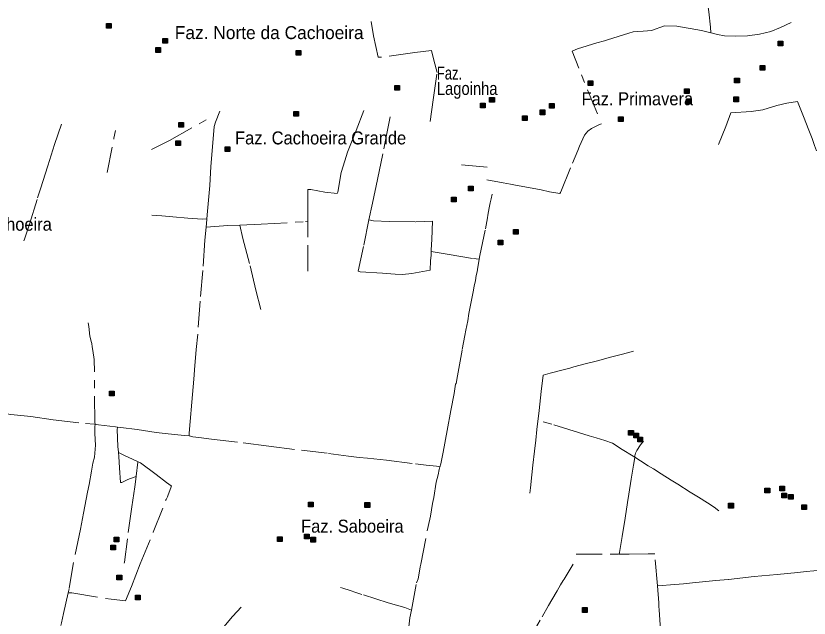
# Model space of a CAD drawing. Extents: x 393.5 to 446.9, y 8064.8 to 8120.4.
# Drawn here: x 415.2 to 425, y 8086.21 to 8093.64 of the extents above; entities that cross this region are included whole.
import ezdxf

# ---------------------------------------------------------------- set-up
doc = ezdxf.new("R2010")
doc.units = 0
doc.header["$LTSCALE"] = 0.064
doc.linetypes.add('DOT_DASHED', pattern=[7.7, 5, -1.2, 0.3, -1.2])
doc.layers.add('2', color=7, linetype='Continuous', lineweight=25)
doc.layers.add('22', color=7, linetype='DOT_DASHED', lineweight=13)
doc.layers.add('61', color=7, linetype='Continuous')

msp = doc.modelspace()

# ---------------------------------------------------------------- hatches: boundary and pattern name
at = {"layer": '2'}
for points in [[(416.3204, 8093.5485), (416.3784, 8093.5485), (416.3784, 8093.4905), (416.3204, 8093.4905)], [(417.0173, 8093.3619), (417.0753, 8093.3619), (417.0753, 8093.3039), (417.0173, 8093.3039)], [(424.6135, 8093.3276), (424.6715, 8093.3276), (424.6715, 8093.2696), (424.6135, 8093.2696)], [(416.9306, 8093.2488), (416.9886, 8093.2488), (416.9886, 8093.1908), (416.9306, 8093.1908)], [(418.6616, 8093.2136), (418.7196, 8093.2136), (418.7196, 8093.1556), (418.6616, 8093.1556)], [(424.3893, 8093.027), (424.4473, 8093.027), (424.4473, 8092.969), (424.3893, 8092.969)], [(422.2669, 8092.8375), (422.3249, 8092.8375), (422.3249, 8092.7795), (422.2669, 8092.7795)], [(424.0763, 8092.8721), (424.1343, 8092.8721), (424.1343, 8092.8141), (424.0763, 8092.8141)], [(419.8802, 8092.7813), (419.9382, 8092.7813), (419.9382, 8092.7233), (419.8802, 8092.7233)], [(423.4581, 8092.7423), (423.5161, 8092.7423), (423.5161, 8092.6843), (423.4581, 8092.6843)], [(421.0516, 8092.6337), (421.1096, 8092.6337), (421.1096, 8092.5757), (421.0516, 8092.5757)], [(424.0649, 8092.6396), (424.1229, 8092.6396), (424.1229, 8092.5816), (424.0649, 8092.5816)], [(420.9393, 8092.5634), (420.9973, 8092.5634), (420.9973, 8092.5054), (420.9393, 8092.5054)], [(421.792, 8092.5595), (421.85, 8092.5595), (421.85, 8092.5015), (421.792, 8092.5015)], [(423.4825, 8092.6149), (423.5405, 8092.6149), (423.5405, 8092.5569), (423.4825, 8092.5569)], [(418.6337, 8092.4601), (418.6917, 8092.4601), (418.6917, 8092.4021), (418.6337, 8092.4021)], [(421.6764, 8092.4793), (421.7344, 8092.4793), (421.7344, 8092.4213), (421.6764, 8092.4213)], [(421.4586, 8092.4089), (421.5166, 8092.4089), (421.5166, 8092.3509), (421.4586, 8092.3509)], [(422.6422, 8092.3944), (422.7002, 8092.3944), (422.7002, 8092.3364), (422.6422, 8092.3364)], [(417.2164, 8092.3236), (417.2744, 8092.3236), (417.2744, 8092.2656), (417.2164, 8092.2656)], [(417.1778, 8092.0993), (417.2358, 8092.0993), (417.2358, 8092.0413), (417.1778, 8092.0413)], [(417.7874, 8092.0233), (417.8454, 8092.0233), (417.8454, 8091.9653), (417.7874, 8091.9653)], [(420.7916, 8091.5372), (420.8496, 8091.5372), (420.8496, 8091.4792), (420.7916, 8091.4792)], [(420.5814, 8091.4037), (420.6394, 8091.4037), (420.6394, 8091.3457), (420.5814, 8091.3457)], [(421.3466, 8091.0041), (421.4046, 8091.0041), (421.4046, 8090.9461), (421.3466, 8090.9461)], [(421.1572, 8090.8707), (421.2152, 8090.8707), (421.2152, 8090.8127), (421.1572, 8090.8127)], [(416.3583, 8089.0062), (416.4163, 8089.0062), (416.4163, 8088.9482), (416.3583, 8088.9482)], [(422.7676, 8088.5222), (422.8256, 8088.5222), (422.8256, 8088.4642), (422.7676, 8088.4642)], [(422.83, 8088.4886), (422.888, 8088.4886), (422.888, 8088.4306), (422.83, 8088.4306)], [(422.8792, 8088.4417), (422.9372, 8088.4417), (422.9372, 8088.3837), (422.8792, 8088.3837)], [(424.6356, 8087.8336), (424.6936, 8087.8336), (424.6936, 8087.7756), (424.6356, 8087.7756)], [(424.4508, 8087.8113), (424.5088, 8087.8113), (424.5088, 8087.7533), (424.4508, 8087.7533)], [(424.6567, 8087.7493), (424.7147, 8087.7493), (424.7147, 8087.6913), (424.6567, 8087.6913)], [(424.7416, 8087.7304), (424.7996, 8087.7304), (424.7996, 8087.6724), (424.7416, 8087.6724)], [(418.8136, 8087.6368), (418.8716, 8087.6368), (418.8716, 8087.5788), (418.8136, 8087.5788)], [(419.5128, 8087.6311), (419.5708, 8087.6311), (419.5708, 8087.5731), (419.5128, 8087.5731)], [(424.0022, 8087.6228), (424.0602, 8087.6228), (424.0602, 8087.5648), (424.0022, 8087.5648)], [(424.9044, 8087.603), (424.9624, 8087.603), (424.9624, 8087.545), (424.9044, 8087.545)], [(418.7651, 8087.244), (418.8231, 8087.244), (418.8231, 8087.186), (418.7651, 8087.186)], [(416.4172, 8087.2035), (416.4752, 8087.2035), (416.4752, 8087.1455), (416.4172, 8087.1455)], [(418.434, 8087.2093), (418.492, 8087.2093), (418.492, 8087.1513), (418.434, 8087.1513)], [(418.8452, 8087.203), (418.9032, 8087.203), (418.9032, 8087.145), (418.8452, 8087.145)], [(416.3753, 8087.1052), (416.4333, 8087.1052), (416.4333, 8087.0472), (416.3753, 8087.0472)], [(416.4513, 8086.7357), (416.5093, 8086.7357), (416.5093, 8086.6777), (416.4513, 8086.6777)], [(416.6809, 8086.4891), (416.7389, 8086.4891), (416.7389, 8086.4311), (416.6809, 8086.4311)], [(422.1961, 8086.335), (422.2541, 8086.335), (422.2541, 8086.277), (422.1961, 8086.277)]]:
    msp.add_hatch(color=256, dxfattribs=at).paths.add_polyline_path(points)

# ---------------------------------------------------------------- linework, layer by layer
for points in [[(416.3204, 8093.5485), (416.3784, 8093.5485), (416.3784, 8093.4905), (416.3204, 8093.4905)], [(417.0173, 8093.3619), (417.0753, 8093.3619), (417.0753, 8093.3039), (417.0173, 8093.3039)], [(424.6135, 8093.3276), (424.6715, 8093.3276), (424.6715, 8093.2696), (424.6135, 8093.2696)], [(416.9306, 8093.2488), (416.9886, 8093.2488), (416.9886, 8093.1908), (416.9306, 8093.1908)], [(418.6616, 8093.2136), (418.7196, 8093.2136), (418.7196, 8093.1556), (418.6616, 8093.1556)], [(424.3893, 8093.027), (424.4473, 8093.027), (424.4473, 8092.969), (424.3893, 8092.969)], [(422.2669, 8092.8375), (422.3249, 8092.8375), (422.3249, 8092.7795), (422.2669, 8092.7795)], [(424.0763, 8092.8721), (424.1343, 8092.8721), (424.1343, 8092.8141), (424.0763, 8092.8141)], [(419.8802, 8092.7813), (419.9382, 8092.7813), (419.9382, 8092.7233), (419.8802, 8092.7233)], [(423.4581, 8092.7423), (423.5161, 8092.7423), (423.5161, 8092.6843), (423.4581, 8092.6843)], [(421.0516, 8092.6337), (421.1096, 8092.6337), (421.1096, 8092.5757), (421.0516, 8092.5757)], [(424.0649, 8092.6396), (424.1229, 8092.6396), (424.1229, 8092.5816), (424.0649, 8092.5816)], [(420.9393, 8092.5634), (420.9973, 8092.5634), (420.9973, 8092.5054), (420.9393, 8092.5054)], [(421.792, 8092.5595), (421.85, 8092.5595), (421.85, 8092.5015), (421.792, 8092.5015)], [(423.4825, 8092.6149), (423.5405, 8092.6149), (423.5405, 8092.5569), (423.4825, 8092.5569)], [(418.6337, 8092.4601), (418.6917, 8092.4601), (418.6917, 8092.4021), (418.6337, 8092.4021)], [(421.6764, 8092.4793), (421.7344, 8092.4793), (421.7344, 8092.4213), (421.6764, 8092.4213)], [(421.4586, 8092.4089), (421.5166, 8092.4089), (421.5166, 8092.3509), (421.4586, 8092.3509)], [(422.6422, 8092.3944), (422.7002, 8092.3944), (422.7002, 8092.3364), (422.6422, 8092.3364)], [(417.2164, 8092.3236), (417.2744, 8092.3236), (417.2744, 8092.2656), (417.2164, 8092.2656)], [(417.1778, 8092.0993), (417.2358, 8092.0993), (417.2358, 8092.0413), (417.1778, 8092.0413)], [(417.7874, 8092.0233), (417.8454, 8092.0233), (417.8454, 8091.9653), (417.7874, 8091.9653)], [(420.7916, 8091.5372), (420.8496, 8091.5372), (420.8496, 8091.4792), (420.7916, 8091.4792)], [(420.5814, 8091.4037), (420.6394, 8091.4037), (420.6394, 8091.3457), (420.5814, 8091.3457)], [(421.3466, 8091.0041), (421.4046, 8091.0041), (421.4046, 8090.9461), (421.3466, 8090.9461)], [(421.1572, 8090.8707), (421.2152, 8090.8707), (421.2152, 8090.8127), (421.1572, 8090.8127)], [(416.3583, 8089.0062), (416.4163, 8089.0062), (416.4163, 8088.9482), (416.3583, 8088.9482)], [(422.7676, 8088.5222), (422.8256, 8088.5222), (422.8256, 8088.4642), (422.7676, 8088.4642)], [(422.83, 8088.4886), (422.888, 8088.4886), (422.888, 8088.4306), (422.83, 8088.4306)], [(422.8792, 8088.4417), (422.9372, 8088.4417), (422.9372, 8088.3837), (422.8792, 8088.3837)], [(424.6356, 8087.8336), (424.6936, 8087.8336), (424.6936, 8087.7756), (424.6356, 8087.7756)], [(424.4508, 8087.8113), (424.5088, 8087.8113), (424.5088, 8087.7533), (424.4508, 8087.7533)], [(424.6567, 8087.7493), (424.7147, 8087.7493), (424.7147, 8087.6913), (424.6567, 8087.6913)], [(424.7416, 8087.7304), (424.7996, 8087.7304), (424.7996, 8087.6724), (424.7416, 8087.6724)], [(418.8136, 8087.6368), (418.8716, 8087.6368), (418.8716, 8087.5788), (418.8136, 8087.5788)], [(419.5128, 8087.6311), (419.5708, 8087.6311), (419.5708, 8087.5731), (419.5128, 8087.5731)], [(424.0022, 8087.6228), (424.0602, 8087.6228), (424.0602, 8087.5648), (424.0022, 8087.5648)], [(424.9044, 8087.603), (424.9624, 8087.603), (424.9624, 8087.545), (424.9044, 8087.545)], [(418.7651, 8087.244), (418.8231, 8087.244), (418.8231, 8087.186), (418.7651, 8087.186)], [(416.4172, 8087.2035), (416.4752, 8087.2035), (416.4752, 8087.1455), (416.4172, 8087.1455)], [(418.434, 8087.2093), (418.492, 8087.2093), (418.492, 8087.1513), (418.434, 8087.1513)], [(418.8452, 8087.203), (418.9032, 8087.203), (418.9032, 8087.145), (418.8452, 8087.145)], [(416.3753, 8087.1052), (416.4333, 8087.1052), (416.4333, 8087.0472), (416.3753, 8087.0472)], [(416.4513, 8086.7357), (416.5093, 8086.7357), (416.5093, 8086.6777), (416.4513, 8086.6777)], [(416.6809, 8086.4891), (416.7389, 8086.4891), (416.7389, 8086.4311), (416.6809, 8086.4311)], [(422.1961, 8086.335), (422.2541, 8086.335), (422.2541, 8086.277), (422.1961, 8086.277)]]:
    msp.add_lwpolyline(points, close=True, dxfattribs=at)
at = {"layer": '22'}
for p, q in [((421.021, 8091.7734), (420.6902, 8091.805)), ((416.8813, 8091.1815), (417.0055, 8091.1705)), ((415.3021, 8090.8647), (415.3099, 8090.8841)), ((416.4682, 8088.2515), (416.4737, 8088.2026)), ((422.8443, 8088.1933), (422.8437, 8088.19)), ((423.1221, 8086.6048), (423.1389, 8086.3932))]:
    msp.add_line(p, q, dxfattribs=at)
for points in [[(423.7013, 8094.0907), (423.7164, 8093.9903), (423.7568, 8093.693), (423.7769, 8093.5017), (423.7823, 8093.4313)], [(420.3187, 8092.3382), (420.356, 8092.603), (420.4032, 8092.9402), (420.3612, 8093.0933), (420.3348, 8093.2117), (420.1269, 8093.1899), (419.7158, 8093.1315), (419.6739, 8093.1297), (419.62, 8093.3957), (419.5872, 8093.5724)], [(423.0006, 8093.4562), (423.0516, 8093.459), (423.2091, 8093.519), (423.3643, 8093.5125), (423.6681, 8093.4607), (423.7823, 8093.4313), (423.787, 8093.4301)], [(423.787, 8093.4301), (423.8658, 8093.412), (423.9496, 8093.3937), (424.0899, 8093.3896), (424.2366, 8093.3957), (424.3811, 8093.414), (424.5236, 8093.4465), (424.6409, 8093.4974), (424.7749, 8093.5604)], [(422.3832, 8092.4302), (422.1509, 8092.9958), (422.0713, 8093.2072), (422.1362, 8093.2336), (422.3761, 8093.3098), (422.4714, 8093.3332), (422.5046, 8093.3455), (422.7704, 8093.4264), (422.8228, 8093.4427), (422.873, 8093.4468), (422.9463, 8093.4508), (423.0006, 8093.4562)], [(423.878, 8092.0514), (423.966, 8092.2735), (424.0289, 8092.4449), (424.2789, 8092.4591), (424.3646, 8092.4716), (424.4225, 8092.4799), (424.5962, 8092.5361), (424.7205, 8092.5652), (424.8513, 8092.586), (424.8749, 8092.5215), (424.9242, 8092.3988), (424.9905, 8092.2306), (425.0312, 8092.1266), (425.0633, 8092.0413), (425.0879, 8091.9742)], [(417.5608, 8091.135), (417.567, 8091.2317), (417.596, 8091.5481), (417.6115, 8091.7829), (417.6324, 8092.0226), (417.6517, 8092.2757), (417.6681, 8092.3286), (417.7229, 8092.4655)], [(419.4973, 8092.4713), (419.4036, 8092.2266), (419.2959, 8091.9573), (419.2632, 8091.8496), (419.2186, 8091.7076), (419.1768, 8091.4665), (419.1697, 8091.4477), (419.0154, 8091.4665), (418.8424, 8091.4991), (418.8074, 8091.4991), (418.8077, 8091.2792), (418.8086, 8091.1075), (418.8086, 8091.1055)], [(416.8761, 8091.99), (417.0977, 8092.1037), (417.5896, 8092.3779)], [(419.5619, 8091.1223), (419.6048, 8091.3307), (419.6685, 8091.6225), (419.7452, 8092.0012), (419.7636, 8092.0876), (419.8251, 8092.3931)], [(415.5071, 8091.5041), (415.5983, 8091.7881), (415.6813, 8092.0549), (415.7674, 8092.3061)], [(421.9317, 8091.4673), (422.073, 8091.8241), (422.1393, 8091.981), (422.1595, 8092.0319), (422.2212, 8092.1679), (422.2629, 8092.2194), (422.3084, 8092.2488), (422.3577, 8092.2764), (422.409, 8092.3012), (422.4331, 8092.3099)], [(416.3301, 8091.7054), (416.4138, 8092.1304), (416.4328, 8092.2239)], [(421.0166, 8091.6154), (421.2166, 8091.5792), (421.308, 8091.5617), (421.3716, 8091.5496), (421.5317, 8091.5226), (421.6884, 8091.4921), (421.7921, 8091.4691), (421.9195, 8091.4479), (421.9268, 8091.4585), (421.9317, 8091.4673)], [(415.3099, 8090.8841), (415.3698, 8091.0676), (415.4706, 8091.3932), (415.5071, 8091.5041)], [(421.0244, 8091.1462), (421.0305, 8091.1795), (421.0478, 8091.2716), (421.0589, 8091.3321), (421.0713, 8091.3818), (421.0824, 8091.4395)], [(417.0055, 8091.1705), (417.1406, 8091.1596), (417.3269, 8091.145), (417.5022, 8091.1304), (417.5608, 8091.135)], [(417.5608, 8091.135), (417.5604, 8091.1284), (417.5539, 8091.0308), (417.5539, 8091.0304)], [(417.5539, 8091.0304), (417.8207, 8091.0518), (417.9666, 8091.0576)], [(417.9666, 8091.0576), (418.2325, 8091.068), (418.7776, 8091.1019), (418.8081, 8091.1055)], [(417.9666, 8091.0576), (418.0068, 8090.8922), (418.0951, 8090.5543), (418.1649, 8090.2562), (418.2291, 8090.0169)], [(418.8086, 8090.4892), (418.8081, 8090.98), (418.8081, 8091.1047), (418.8081, 8091.1055)], [(419.5619, 8091.1223), (419.4941, 8090.793), (419.4279, 8090.488), (419.4527, 8090.4798), (419.7279, 8090.4632), (419.8872, 8090.4529), (419.9765, 8090.4485), (420.09, 8090.4591), (420.3156, 8090.5004), (420.3218, 8090.6162), (420.3286, 8090.6883), (420.3314, 8090.7308)], [(419.5619, 8091.1223), (419.6162, 8091.1119), (419.8107, 8091.1015), (420.1397, 8091.0995), (420.3445, 8091.1057), (420.3362, 8090.8782), (420.33, 8090.7506), (420.3314, 8090.7308)], [(420.9207, 8090.6362), (420.9318, 8090.6812), (420.9996, 8091.0109), (421.0162, 8091.1035), (421.0244, 8091.1462)], [(417.5539, 8091.0308), (417.5366, 8090.8703), (417.5094, 8090.4973), (417.4788, 8090.1188), (417.4482, 8089.7093), (417.4291, 8089.5227), (417.4081, 8089.2726), (417.4039, 8089.2103)], [(420.3314, 8090.7308), (420.5255, 8090.6981), (420.8528, 8090.6443), (420.9177, 8090.6366), (420.9207, 8090.6362)], [(420.6391, 8089.104), (420.6563, 8089.1977), (420.7118, 8089.5208), (420.7464, 8089.6953), (420.7589, 8089.7625), (420.7809, 8089.8743), (420.7948, 8089.9683), (420.8294, 8090.1322), (420.8487, 8090.2343), (420.8625, 8090.3032), (420.8791, 8090.3757), (420.8847, 8090.4375), (420.8971, 8090.4791), (420.9068, 8090.5368), (420.9193, 8090.6086), (420.9207, 8090.6362)], [(416.14, 8089.5957), (416.1374, 8089.6085), (416.1179, 8089.686), (416.1048, 8089.8065), (416.095, 8089.85)], [(416.1809, 8088.6013), (416.1785, 8088.6251), (416.171, 8089.3966), (416.1547, 8089.5117), (416.146, 8089.5563), (416.14, 8089.5957)], [(422.8284, 8089.5012), (422.6916, 8089.4643), (422.5421, 8089.4275), (422.3825, 8089.3832), (422.2305, 8089.3439), (422.0901, 8089.3066)], [(422.0901, 8089.3066), (422.0401, 8089.2929), (421.9421, 8089.268), (421.7974, 8089.2285), (421.7114, 8089.2051), (421.6873, 8089.0053), (421.6617, 8088.7676), (421.6361, 8088.5342), (421.621, 8088.404), (421.6059, 8088.2679), (421.5848, 8088.0924), (421.5712, 8087.9754), (421.5547, 8087.8122), (421.5472, 8087.7464)], [(417.4039, 8089.2103), (417.4007, 8089.1541), (417.376, 8088.8732), (417.3559, 8088.6342), (417.3442, 8088.491), (417.3442, 8088.4545)], [(420.4368, 8088.0712), (420.4503, 8088.1094), (420.4772, 8088.2559), (420.5291, 8088.5227), (420.5721, 8088.769), (420.6122, 8088.9785), (420.6316, 8089.0921), (420.6391, 8089.104)], [(414.9968, 8088.7422), (415.1424, 8088.7193), (415.388, 8088.6931), (415.6638, 8088.6555), (416.0625, 8088.6082), (416.1753, 8088.6016), (416.1766, 8088.6015), (416.1809, 8088.6013)], [(422.8443, 8088.1933), (422.8217, 8088.205), (422.689, 8088.2856), (422.5683, 8088.3638), (422.4718, 8088.4004), (422.3678, 8088.4311), (422.2803, 8088.4575), (422.1476, 8088.4955), (421.8199, 8088.5997), (421.7144, 8088.6304)], [(416.1809, 8088.6013), (416.1768, 8088.5662), (416.1768, 8088.4844), (416.185, 8088.3421), (416.1736, 8088.1908), (416.1539, 8088.1204), (416.1375, 8088.0213), (416.1088, 8087.8571)], [(416.4576, 8088.5621), (416.4331, 8088.5653), (416.2219, 8088.5932), (416.1825, 8088.601), (416.1809, 8088.6013)], [(416.4576, 8088.5621), (416.4576, 8088.5618), (416.4575, 8088.5605), (416.4575, 8088.5603), (416.4556, 8088.533)], [(416.4556, 8088.533), (416.463, 8088.3238), (416.4681, 8088.2527), (416.4682, 8088.2515)], [(416.4576, 8088.5621), (416.4986, 8088.5588), (416.7006, 8088.5327), (416.9347, 8088.4984), (417.0846, 8088.4825)], [(417.0846, 8088.4825), (417.1671, 8088.4746), (417.2803, 8088.46), (417.3442, 8088.4545)], [(417.3442, 8088.4545), (417.388, 8088.4454), (417.4628, 8088.4346), (417.6202, 8088.417), (418.0078, 8088.3682), (418.3261, 8088.3289), (418.73, 8088.2773), (419.0644, 8088.2394), (419.3081, 8088.2042), (419.4397, 8088.1866), (419.5442, 8088.1798), (419.7784, 8088.154), (420.1364, 8088.1093), (420.2683, 8088.0925), (420.3959, 8088.0799), (420.4357, 8088.0714), (420.4368, 8088.0712)], [(422.9498, 8088.3908), (422.9152, 8088.344), (422.8699, 8088.2767), (422.8503, 8088.2416), (422.8443, 8088.2094), (422.8443, 8088.1933)], [(416.7061, 8088.1409), (416.5378, 8088.2189), (416.4682, 8088.2515)], [(416.4737, 8088.2026), (416.4821, 8088.06), (416.4954, 8087.8793), (416.5095, 8087.8804), (416.5856, 8087.9173), (416.6628, 8087.9478), (416.689, 8087.9552)], [(416.7095, 8088.1291), (416.6892, 8087.9566), (416.689, 8087.9552)], [(416.7061, 8088.1409), (416.7419, 8088.1224), (416.9351, 8087.9796), (417.0634, 8087.8808), (417.1211, 8087.8399), (417.1232, 8087.8384)], [(422.8437, 8088.19), (422.8274, 8088.0957), (422.8002, 8087.9224), (422.7715, 8087.7372), (422.7549, 8087.6348), (422.7249, 8087.4409), (422.6857, 8087.2141), (422.656, 8087.014), (422.6521, 8086.9969)], [(423.8807, 8087.531), (423.8214, 8087.5743), (423.74, 8087.627), (423.6284, 8087.6972), (423.5289, 8087.7601), (423.375, 8087.859), (423.2936, 8087.9087), (423.17, 8087.9863), (423.0734, 8088.0477), (423.0101, 8088.0858), (422.9121, 8088.1494), (422.8443, 8088.1933)], [(420.1948, 8086.8375), (420.2014, 8086.8726), (420.2911, 8087.335), (420.3196, 8087.4638), (420.3454, 8087.6198), (420.3629, 8087.6943), (420.3929, 8087.8827), (420.416, 8087.9736), (420.4305, 8088.0422), (420.4357, 8088.0714)], [(416.689, 8087.9552), (416.6737, 8087.826), (416.6362, 8087.581), (416.5794, 8087.1842), (416.5438, 8086.8976), (416.5392, 8086.8823)], [(416.1088, 8087.8571), (416.087, 8087.7618), (416.0374, 8087.5034), (416.002, 8087.3036), (415.9164, 8086.8922), (415.8599, 8086.5671), (415.8501, 8086.5197)], [(417.0738, 8087.7043), (417.0788, 8087.7169), (417.1189, 8087.8262), (417.1232, 8087.8384)], [(415.8943, 8086.5164), (416.3784, 8086.4385), (416.5552, 8086.4177), (416.6307, 8086.597), (416.7391, 8086.8752), (416.8997, 8087.2655), (417.0569, 8087.6692), (417.0738, 8087.7043)], [(422.1204, 8086.9946), (422.65, 8086.9969), (422.6515, 8086.9969), (422.6521, 8086.9969)], [(423.0106, 8086.9992), (422.7729, 8086.9972), (422.6521, 8086.9969)], [(423.1221, 8086.6048), (423.0905, 8086.9975), (423.0498, 8086.9975), (423.0106, 8086.9992)], [(421.97, 8086.6847), (422.0197, 8086.7673), (422.0576, 8086.829), (422.0833, 8086.8717)], [(420.0857, 8086.3044), (420.086, 8086.3056), (420.1502, 8086.6397), (420.1678, 8086.6926), (420.1841, 8086.7861), (420.1948, 8086.8375)], [(425.3536, 8086.8228), (425.2194, 8086.8097), (425.1486, 8086.7973), (424.9586, 8086.7812), (424.8561, 8086.768), (424.6013, 8086.7438), (424.3164, 8086.7182), (423.9967, 8086.6838), (423.8444, 8086.6707), (423.5564, 8086.6422), (423.4434, 8086.6305), (423.2835, 8086.6159), (423.1795, 8086.6071), (423.1221, 8086.6048)], [(421.3051, 8085.5431), (421.3056, 8085.5476), (421.3369, 8085.6093), (421.4233, 8085.7534), (421.4899, 8085.8666), (421.5152, 8085.9046), (421.6987, 8086.2226), (421.7775, 8086.3608), (421.8199, 8086.4313), (421.8848, 8086.5409), (421.9273, 8086.6173), (421.9591, 8086.6688), (421.97, 8086.6847)], [(420.086, 8086.3056), (420.0049, 8086.3353), (419.8006, 8086.395), (419.4734, 8086.4992), (419.3988, 8086.5236), (419.3295, 8086.548), (419.24, 8086.5738), (419.2115, 8086.5833)], [(415.8501, 8086.5197), (415.7926, 8086.2646), (415.7668, 8086.1479), (415.7586, 8086.1136)], [(415.8501, 8086.5197), (415.8534, 8086.5195), (415.8943, 8086.5164)], [(423.1389, 8086.3932), (423.1404, 8086.3494), (423.1449, 8086.3069), (423.1616, 8086.0618), (423.1782, 8085.8299), (423.1932, 8085.5979), (423.2083, 8085.4457), (423.2279, 8085.1793), (423.241, 8084.9987), (423.3091, 8085.0015), (423.3104, 8085.0016), (423.3119, 8085.0017)], [(417.8775, 8086.226), (417.8819, 8086.2315), (417.985, 8086.3426)], [(420.0298, 8085.8798), (420.0395, 8085.9557), (420.0671, 8086.2082), (420.0856, 8086.3037), (420.086, 8086.3056)], [(416.2424, 8084.3421), (416.2595, 8084.3618), (416.4661, 8084.5948), (416.5934, 8084.7467), (416.8024, 8084.977), (417.0045, 8085.2141), (417.4162, 8085.684), (417.5028, 8085.7824), (417.7527, 8086.0777), (417.7896, 8086.1215), (417.8775, 8086.226)]]:
    msp.add_lwpolyline(points, dxfattribs=at)

# ---------------------------------------------------------------- texts
at = {"layer": '61'}
msp.add_text('Faz. Norte da Cachoeira', height=0.16, dxfattribs=at).set_placement((417.1649, 8093.3544))
for s, width, p in [('Faz.', 0.75, (420.4004, 8092.8549)), ('Lagoinha', 0.85, (420.4004, 8092.6649)), ('Faz. Primavera', 0.95, (422.1859, 8092.5374)), ('Faz. Cachoeira Grande', 0.95, (417.9088, 8092.0543)), ('Faz. Cachoeira', 0.95, (414.2694, 8090.9889)), ('Faz. Saboeira', 0.95, (418.7241, 8087.261))]:
    msp.add_text(s, height=0.16, dxfattribs=dict(at, width=width)).set_placement(p)

doc.saveas('drawing.dxf')
